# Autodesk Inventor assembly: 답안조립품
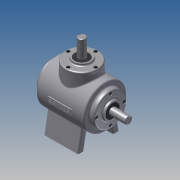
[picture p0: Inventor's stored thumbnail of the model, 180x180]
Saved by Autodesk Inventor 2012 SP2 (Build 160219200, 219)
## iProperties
Created: 2015-01
Part Number: 답안조립품
Document SubType Name: Assembly
Designer: cad-02
Author: cad-02
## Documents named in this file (15)
- C:\Users\cad-02\Desktop\450106V1028\답안조립품.iam
- C:\Users\cad-02\Desktop\450106V1028\본체.ipt
- C:\Users\cad-02\Desktop\450106V1028\커버.ipt
- C:\Users\cad-02\Desktop\450106V1028\커버2.ipt
- C:\Users\cad-02\Desktop\450106V1028\베어링 6203.ipt
- C:\Users\cad-02\Desktop\450106V1028\서브 축.ipt
- 서브 축.ipt
- C:\Users\cad-02\Desktop\450106V1028\키 4x4.ipt
- C:\Users\cad-02\Desktop\450106V1028\메인 축.ipt
- 메인 축.ipt
- C:\Users\cad-02\Desktop\450106V1028\키 5x5.ipt
- C:\Users\cad-02\Desktop\450106V1028\메인 베벨기어.ipt
- C:\Users\cad-02\Desktop\450106V1028\서브 베벨기어.ipt
- C:\Users\cad-02\Desktop\450106V1028\오일실.ipt
- C:\Users\cad-02\Desktop\450106V1028\M4.ipt
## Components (12 placed, 1 different names)
1. M4:1
2. M4:4
3. M4:5
4. M4:6
5. M4:2
6. M4:7
7. M4:8
8. M4:9
9. M4:3
10. M4:10
11. M4:11
12. M4:12
